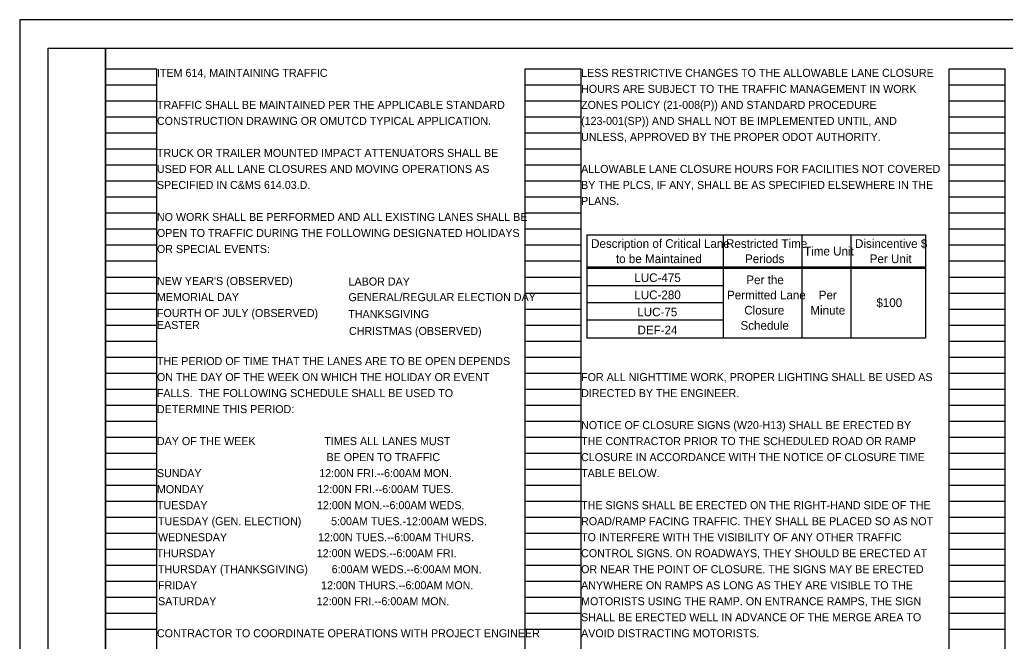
# Model space of a CAD drawing. Extents: x 0 to 34, y 0.1 to 22.1.
# Drawn here: x 0.01 to 17.25, y 11.19 to 22.06 of the extents above; entities that cross this region are included whole.
import ezdxf

# ---------------------------------------------------------------- set-up
doc = ezdxf.new("R2010")
doc.units = 0
for name, color, linetype in [('SC_Scratch1', 7, 'Continuous'), ('SH_Border', 7, 'Continuous'), ('SH_Cut_Line', 7, 'Continuous'), ('SH_Text', 7, 'Continuous')]:
    doc.layers.add(name, color=color, linetype=linetype)

msp = doc.modelspace()

# ---------------------------------------------------------------- linework, layer by layer
at = {"layer": 'SC_Scratch1'}
for p, q in [((1.514, 1.044), (1.514, 21.204)), ((1.514, 21.204), (2.414, 21.204)), ((2.414, 1.044), (2.414, 21.204)), ((8.854, 1.044), (8.854, 21.204)), ((8.854, 21.204), (9.834, 21.204)), ((9.834, 1.044), (9.834, 21.204)), ((16.274, 1.044), (16.274, 21.204)), ((16.274, 21.204), (17.254, 21.204)), ((17.254, 1.044), (17.254, 21.204)), ((1.514, 20.924), (2.414, 20.924)), ((8.854, 20.924), (9.834, 20.924)), ((16.274, 20.924), (17.254, 20.924)), ((1.514, 20.644), (2.414, 20.644)), ((8.854, 20.644), (9.834, 20.644)), ((16.274, 20.644), (17.254, 20.644)), ((1.514, 20.364), (2.414, 20.364)), ((8.854, 20.364), (9.834, 20.364)), ((16.274, 20.364), (17.254, 20.364)), ((1.514, 20.084), (2.414, 20.084)), ((8.854, 20.084), (9.834, 20.084)), ((16.274, 20.084), (17.254, 20.084)), ((1.514, 19.804), (2.414, 19.804)), ((8.854, 19.804), (9.834, 19.804)), ((16.274, 19.804), (17.254, 19.804)), ((1.514, 19.524), (2.414, 19.524)), ((8.854, 19.524), (9.834, 19.524)), ((16.274, 19.524), (17.254, 19.524)), ((1.514, 19.244), (2.414, 19.244)), ((8.854, 19.244), (9.834, 19.244)), ((16.274, 19.244), (17.254, 19.244)), ((1.514, 18.964), (2.414, 18.964)), ((8.854, 18.964), (9.834, 18.964)), ((16.274, 18.964), (17.254, 18.964)), ((1.514, 18.684), (2.414, 18.684)), ((8.854, 18.684), (9.834, 18.684)), ((16.274, 18.684), (17.254, 18.684)), ((1.514, 18.404), (2.414, 18.404)), ((8.854, 18.404), (9.834, 18.404)), ((16.274, 18.404), (17.254, 18.404)), ((1.514, 18.124), (2.414, 18.124)), ((8.854, 18.124), (9.834, 18.124)), ((16.274, 18.124), (17.254, 18.124)), ((1.514, 17.844), (2.414, 17.844)), ((8.854, 17.844), (9.834, 17.844)), ((16.274, 17.844), (17.254, 17.844)), ((1.514, 17.564), (2.414, 17.564)), ((8.854, 17.564), (9.834, 17.564)), ((16.274, 17.564), (17.254, 17.564)), ((1.514, 17.284), (2.414, 17.284)), ((8.854, 17.284), (9.834, 17.284)), ((16.274, 17.284), (17.254, 17.284)), ((1.514, 17.004), (2.414, 17.004)), ((8.854, 17.004), (9.834, 17.004)), ((16.274, 17.004), (17.254, 17.004)), ((1.514, 16.724), (2.414, 16.724)), ((8.854, 16.724), (9.834, 16.724)), ((16.274, 16.724), (17.254, 16.724)), ((1.514, 16.444), (2.414, 16.444)), ((8.854, 16.444), (9.834, 16.444)), ((16.274, 16.444), (17.254, 16.444)), ((1.514, 16.164), (2.414, 16.164)), ((8.854, 16.164), (9.834, 16.164)), ((16.274, 16.164), (17.254, 16.164)), ((1.514, 15.884), (2.414, 15.884)), ((8.854, 15.884), (9.834, 15.884)), ((16.274, 15.884), (17.254, 15.884)), ((1.514, 15.604), (2.414, 15.604)), ((8.854, 15.604), (9.834, 15.604)), ((16.274, 15.604), (17.254, 15.604)), ((1.514, 15.324), (2.414, 15.324)), ((8.854, 15.324), (9.834, 15.324)), ((16.274, 15.324), (17.254, 15.324)), ((1.514, 15.044), (2.414, 15.044)), ((8.854, 15.044), (9.834, 15.044)), ((16.274, 15.044), (17.254, 15.044)), ((1.514, 14.764), (2.414, 14.764)), ((8.854, 14.764), (9.834, 14.764)), ((16.274, 14.764), (17.254, 14.764)), ((1.514, 14.484), (2.414, 14.484)), ((8.854, 14.484), (9.834, 14.484)), ((16.274, 14.484), (17.254, 14.484)), ((1.514, 14.204), (2.414, 14.204)), ((8.854, 14.204), (9.834, 14.204)), ((16.274, 14.204), (17.254, 14.204)), ((1.514, 13.924), (2.414, 13.924)), ((8.854, 13.924), (9.834, 13.924)), ((16.274, 13.924), (17.254, 13.924)), ((1.514, 13.644), (2.414, 13.644)), ((8.854, 13.644), (9.834, 13.644)), ((16.274, 13.644), (17.254, 13.644)), ((1.514, 13.364), (2.414, 13.364)), ((8.854, 13.364), (9.834, 13.364)), ((16.274, 13.364), (17.254, 13.364)), ((1.514, 13.084), (2.414, 13.084)), ((8.854, 13.084), (9.834, 13.084)), ((16.274, 13.084), (17.254, 13.084)), ((1.514, 12.804), (2.414, 12.804)), ((8.854, 12.804), (9.834, 12.804)), ((16.274, 12.804), (17.254, 12.804)), ((1.514, 12.524), (2.414, 12.524)), ((8.854, 12.524), (9.834, 12.524)), ((16.274, 12.524), (17.254, 12.524)), ((1.514, 12.244), (2.414, 12.244)), ((8.854, 12.244), (9.834, 12.244)), ((16.274, 12.244), (17.254, 12.244)), ((1.514, 11.964), (2.414, 11.964)), ((8.854, 11.964), (9.834, 11.964)), ((16.274, 11.964), (17.254, 11.964)), ((1.514, 11.684), (2.414, 11.684)), ((8.854, 11.684), (9.834, 11.684)), ((16.274, 11.684), (17.254, 11.684)), ((1.514, 11.404), (2.414, 11.404)), ((8.854, 11.404), (9.834, 11.404)), ((16.274, 11.404), (17.254, 11.404))]:
    msp.add_line(p, q, dxfattribs=at)
at = {"layer": 'SH_Border'}
for points in [[(0.514, 21.564), (1.514, 21.564), (1.514, 0.564), (0.514, 0.564)], [(1.514, 21.564), (33.514, 21.564), (33.514, 0.564), (1.514, 0.564)]]:
    msp.add_lwpolyline(points, close=True, dxfattribs=at)
at = {"layer": 'SH_Cut_Line'}
msp.add_lwpolyline([(0.014, 0.064), (34.014, 0.064), (34.014, 22.064), (0.014, 22.064)], close=True, dxfattribs=at)
at = {"layer": 'SH_Text'}
for p, q in [((9.932, 18.301), (15.857, 18.301)), ((9.932, 18.301), (9.932, 17.721)), ((12.317, 18.301), (12.317, 17.741)), ((13.697, 18.301), (13.697, 17.741)), ((14.552, 18.301), (14.552, 17.741)), ((15.857, 18.301), (15.857, 17.721)), ((9.932, 17.741), (15.857, 17.741)), ((9.932, 17.741), (9.932, 16.501)), ((9.932, 17.721), (15.857, 17.721)), ((12.317, 17.721), (12.317, 16.501)), ((13.697, 17.721), (13.697, 16.501)), ((14.552, 17.721), (14.552, 16.501)), ((15.857, 17.741), (15.857, 16.501)), ((9.932, 17.416), (12.317, 17.416)), ((9.932, 17.116), (12.317, 17.116)), ((9.932, 16.816), (12.317, 16.816)), ((9.932, 16.501), (15.857, 16.501))]:
    msp.add_line(p, q, dxfattribs=at)

# ---------------------------------------------------------------- texts
for s, height, p in [('ITEM 614, MAINTAINING TRAFFIC', 0.14, (2.414, 21.064)), ('LESS RESTRICTIVE CHANGES TO THE ALLOWABLE LANE CLOSURE', 0.14, (9.834, 21.064)), ('HOURS ARE SUBJECT TO THE TRAFFIC MANAGEMENT IN WORK', 0.14, (9.834, 20.784)), ('TRAFFIC SHALL BE MAINTAINED PER THE APPLICABLE STANDARD', 0.14, (2.414, 20.504)), ('ZONES POLICY (21-008(P)) AND STANDARD PROCEDURE', 0.14, (9.834, 20.504)), ('CONSTRUCTION DRAWING OR OMUTCD TYPICAL APPLICATION.', 0.14, (2.414, 20.224)), ('(123-001(SP)) AND SHALL NOT BE IMPLEMENTED UNTIL, AND', 0.14, (9.834, 20.224)), ('UNLESS, APPROVED BY THE PROPER ODOT AUTHORITY.', 0.14, (9.834, 19.944)), ('TRUCK OR TRAILER MOUNTED IMPACT ATTENUATORS SHALL BE', 0.14, (2.414, 19.664)), ('USED FOR ALL LANE CLOSURES AND MOVING OPERATIONS AS', 0.14, (2.414, 19.384)), ('ALLOWABLE LANE CLOSURE HOURS FOR FACILITIES NOT COVERED', 0.14, (9.834, 19.384)), ('SPECIFIED IN C&MS 614.03.D.', 0.14, (2.414, 19.104)), ('BY THE PLCS, IF ANY, SHALL BE AS SPECIFIED ELSEWHERE IN THE', 0.14, (9.834, 19.104)), ('PLANS.', 0.14, (9.834, 18.824)), ('NO WORK SHALL BE PERFORMED AND ALL EXISTING LANES SHALL BE', 0.14, (2.414, 18.544)), ('OPEN TO TRAFFIC DURING THE FOLLOWING DESIGNATED HOLIDAYS', 0.14, (2.414, 18.264)), ('OR SPECIAL EVENTS:', 0.14, (2.414, 17.984)), ('Description of Critical Lane ', 0.1518, (10.009, 18.073)), ('Restricted Time ', 0.1518, (12.369, 18.073)), ('Disincentive $ ', 0.1518, (14.626, 18.073)), ('to be Maintained', 0.1518, (10.444, 17.807)), ('Periods', 0.1518, (12.702, 17.807)), ('Time Unit', 0.1518, (13.736, 17.94)), ('Per Unit', 0.1518, (14.883, 17.807)), ('LUC-475', 0.1518, (10.765, 17.476)), ('Per the ', 0.1518, (12.725, 17.439)), ("NEW YEAR'S (OBSERVED) ", 0.14, (2.414, 17.424)), (' LABOR DAY', 0.14, (5.715, 17.415)), ('MEMORIAL DAY', 0.14, (2.414, 17.144)), ('GENERAL/REGULAR ELECTION DAY', 0.14, (5.765, 17.142)), ('LUC-280', 0.1518, (10.765, 17.176)), ('Permitted Lane ', 0.1518, (12.387, 17.173)), ('Per ', 0.1518, (13.992, 17.173)), ('$100', 0.1518, (14.999, 17.04)), ('FOURTH OF JULY (OBSERVED)', 0.14, (2.414, 16.864)), ('THANKSGIVING', 0.14, (5.762, 16.846)), ('LUC-75', 0.1518, (10.817, 16.876)), ('Closure ', 0.1518, (12.689, 16.907)), ('Minute', 0.1518, (13.845, 16.907)), ('EASTER', 0.14, (2.414, 16.654)), ('Schedule', 0.1518, (12.622, 16.642)), ('CHRISTMAS (OBSERVED)', 0.14, (5.774, 16.55)), ('DEF-24', 0.1518, (10.821, 16.561)), ('THE PERIOD OF TIME THAT THE LANES ARE TO BE OPEN DEPENDS', 0.14, (2.414, 16.024)), ('ON THE DAY OF THE WEEK ON WHICH THE HOLIDAY OR EVENT', 0.14, (2.414, 15.744)), ('FOR ALL NIGHTTIME WORK, PROPER LIGHTING SHALL BE USED AS', 0.14, (9.834, 15.744)), ('FALLS.  THE FOLLOWING SCHEDULE SHALL BE USED TO', 0.14, (2.414, 15.464)), ('DIRECTED BY THE ENGINEER.  ', 0.14, (9.834, 15.464)), ('DETERMINE THIS PERIOD:', 0.14, (2.414, 15.184)), ('NOTICE OF CLOSURE SIGNS (W20-H13) SHALL BE ERECTED BY', 0.14, (9.834, 14.904)), ('DAY OF THE WEEK', 0.14, (2.414, 14.624)), ('TIMES ALL LANES MUST', 0.14, (5.342, 14.624)), ('THE CONTRACTOR PRIOR TO THE SCHEDULED ROAD OR RAMP', 0.14, (9.834, 14.624)), ('BE OPEN TO TRAFFIC', 0.14, (5.381, 14.344)), ('CLOSURE IN ACCORDANCE WITH THE NOTICE OF CLOSURE TIME', 0.14, (9.834, 14.344)), ('SUNDAY', 0.14, (2.414, 14.064)), ('                   12:00N FRI.--6:00AM MON.', 0.14, (4.265, 14.064)), ('TABLE BELOW. ', 0.14, (9.834, 14.064)), ('MONDAY', 0.14, (2.414, 13.784)), ('                  12:00N FRI.--6:00AM TUES.', 0.14, (4.284, 13.784)), ('TUESDAY                     ', 0.14, (2.414, 13.504)), ('12:00N MON.--6:00AM WEDS.', 0.14, (5.214, 13.504)), ('THE SIGNS SHALL BE ERECTED ON THE RIGHT-HAND SIDE OF THE', 0.14, (9.834, 13.504)), ('TUESDAY (GEN. ELECTION)          5:00AM TUES.-12:00AM WEDS.', 0.14, (2.434, 13.224)), ('ROAD/RAMP FACING TRAFFIC. THEY SHALL BE PLACED SO AS NOT', 0.14, (9.834, 13.224)), ('WEDNESDAY                  ', 0.14, (2.434, 12.944)), ('12:00N TUES.--6:00AM THURS.', 0.14, (5.234, 12.944)), ('TO INTERFERE WITH THE VISIBILITY OF ANY OTHER TRAFFIC', 0.14, (9.834, 12.944)), ('THURSDAY                    ', 0.14, (2.41, 12.664)), ('12:00N WEDS.--6:00AM FRI.', 0.14, (5.21, 12.664)), ('CONTROL SIGNS. ON ROADWAYS, THEY SHOULD BE ERECTED AT', 0.14, (9.834, 12.664)), ('THURSDAY (THANKSGIVING)        6:00AM WEDS.--6:00AM MON.', 0.14, (2.434, 12.384)), ('OR NEAR THE POINT OF CLOSURE. THE SIGNS MAY BE ERECTED', 0.14, (9.834, 12.384)), ('FRIDAY                      ', 0.14, (2.434, 12.104)), (' 12:00N THURS.--6:00AM MON.', 0.14, (5.234, 12.104)), ('ANYWHERE ON RAMPS AS LONG AS THEY ARE VISIBLE TO THE', 0.14, (9.834, 12.104)), ('SATURDAY', 0.14, (2.434, 11.824)), ('  12:00N FRI.--6:00AM MON.', 0.14, (5.104, 11.824)), ('MOTORISTS USING THE RAMP. ON ENTRANCE RAMPS, THE SIGN', 0.14, (9.834, 11.824)), ('SHALL BE ERECTED WELL IN ADVANCE OF THE MERGE AREA TO', 0.14, (9.834, 11.544)), ('CONTRACTOR TO COORDINATE OPERATIONS WITH PROJECT ENGINEER', 0.14, (2.414, 11.264)), ('AVOID DISTRACTING MOTORISTS.', 0.14, (9.834, 11.264))]:
    msp.add_text(s, height=height, dxfattribs=at).set_placement(p)

doc.saveas('drawing.dxf')
